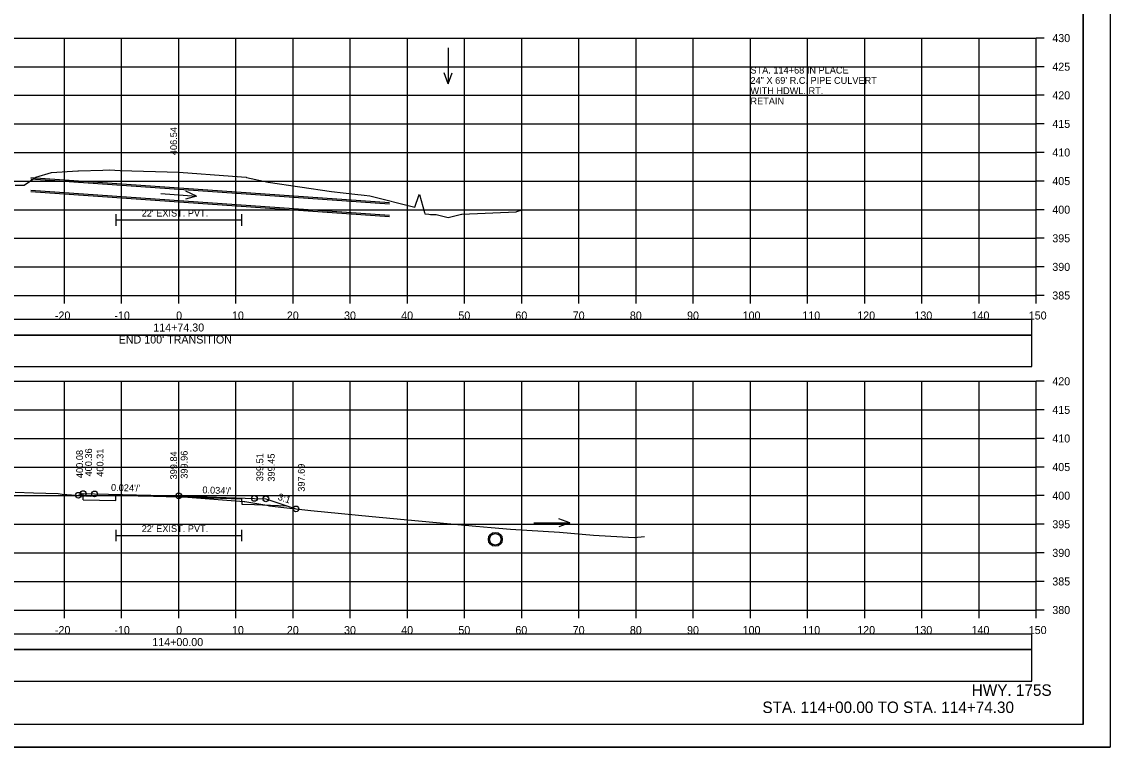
# Model space of a CAD drawing. Extents: x -37291014 to -37290680, y -936053 to -933067.
# Drawn here: x -37290870.6 to -37290680.2, y -933279.9 to -933153.1 of the extents above; entities that cross this region are included whole.
import ezdxf

# ---------------------------------------------------------------- set-up
doc = ezdxf.new("R2010")
doc.units = 0
for name, color, linetype in [('Default', 7, 'Continuous'), ('R_Alt Surface', 7, 'Continuous'), ('R_Axis', 7, 'Continuous'), ('R_Axis Annot', 7, 'Continuous'), ('R_Border', 7, 'Continuous'), ('R_Draft', 7, 'Continuous'), ('R_Exist Surface', 7, 'Continuous'), ('R_Fin Surface', 7, 'Continuous'), ('R_Grid', 7, 'Continuous'), ('R_No Plot', 7, 'Continuous'), ('R_Water', 7, 'Continuous'), ('R_Water Annot', 7, 'Continuous'), ('R_Xsect Elev', 7, 'Continuous'), ('R_Xsect Slope', 7, 'Continuous')]:
    doc.layers.add(name, color=color, linetype=linetype)

msp = doc.modelspace()

# ---------------------------------------------------------------- linework, layer by layer
at = {"layer": 'Default'}
for points in [[(-37290992.31, -933207.84), (-37290693.89, -933207.84), (-37290693.89, -933205.13), (-37290992.31, -933205.13)], [(-37290992.31, -933213.36), (-37290693.89, -933213.36), (-37290693.89, -933207.84), (-37290992.31, -933207.84)], [(-37290992.31, -933262.84), (-37290693.89, -933262.84), (-37290693.89, -933260.13), (-37290992.31, -933260.13)], [(-37290992.31, -933268.36), (-37290693.89, -933268.36), (-37290693.89, -933262.84), (-37290992.31, -933262.84)]]:
    msp.add_lwpolyline(points, close=True, dxfattribs=at)
at = {"layer": 'R_Alt Surface'}
msp.add_line((-37290859.82, -933236.66), (-37290859.82, -933235.57), dxfattribs=at)
for points in [[(-37290854.1, -933186.73), (-37290854.1, -933188.73)], [(-37290854.1, -933187.73), (-37290832.1, -933187.73)], [(-37290832.1, -933186.73), (-37290832.1, -933188.73)], [(-37290859.82, -933236.66), (-37290854.1, -933236.79), (-37290854.1, -933235.87), (-37290843.1, -933236.13), (-37290832.1, -933236.51), (-37290832.09, -933237.43), (-37290829.87, -933237.5), (-37290824.24, -933237.69)], [(-37290854.1, -933241.89), (-37290854.1, -933243.89)], [(-37290854.1, -933242.89), (-37290832.1, -933242.89)], [(-37290832.1, -933241.89), (-37290832.1, -933243.89)]]:
    msp.add_lwpolyline(points, dxfattribs=at)
at = {"layer": 'R_Axis'}
for p, q in [((-37290693.1, -933200.93), (-37290693.1, -933155.93)), ((-37290691.7, -933155.93), (-37290693.1, -933155.93)), ((-37290691.7, -933160.93), (-37290693.1, -933160.93)), ((-37290691.7, -933165.93), (-37290693.1, -933165.93)), ((-37290691.7, -933170.93), (-37290693.1, -933170.93)), ((-37290691.7, -933175.93), (-37290693.1, -933175.93)), ((-37290691.7, -933180.93), (-37290693.1, -933180.93)), ((-37290691.7, -933185.93), (-37290693.1, -933185.93)), ((-37290691.7, -933190.93), (-37290693.1, -933190.93)), ((-37290691.7, -933195.93), (-37290693.1, -933195.93)), ((-37290993.1, -933200.93), (-37290693.1, -933200.93)), ((-37290863.1, -933202.33), (-37290863.1, -933200.93)), ((-37290853.1, -933202.33), (-37290853.1, -933200.93)), ((-37290843.1, -933202.33), (-37290843.1, -933200.93)), ((-37290833.1, -933202.33), (-37290833.1, -933200.93)), ((-37290823.1, -933202.33), (-37290823.1, -933200.93)), ((-37290813.1, -933202.33), (-37290813.1, -933200.93)), ((-37290803.1, -933202.33), (-37290803.1, -933200.93)), ((-37290793.1, -933202.33), (-37290793.1, -933200.93)), ((-37290783.1, -933202.33), (-37290783.1, -933200.93)), ((-37290773.1, -933202.33), (-37290773.1, -933200.93)), ((-37290763.1, -933202.33), (-37290763.1, -933200.93)), ((-37290753.1, -933202.33), (-37290753.1, -933200.93)), ((-37290743.1, -933202.33), (-37290743.1, -933200.93)), ((-37290733.1, -933202.33), (-37290733.1, -933200.93)), ((-37290723.1, -933202.33), (-37290723.1, -933200.93)), ((-37290713.1, -933202.33), (-37290713.1, -933200.93)), ((-37290703.1, -933202.33), (-37290703.1, -933200.93)), ((-37290693.1, -933202.33), (-37290693.1, -933200.93)), ((-37290691.7, -933200.93), (-37290693.1, -933200.93)), ((-37290693.1, -933255.93), (-37290693.1, -933215.93)), ((-37290691.7, -933215.93), (-37290693.1, -933215.93)), ((-37290691.7, -933220.93), (-37290693.1, -933220.93)), ((-37290691.7, -933225.93), (-37290693.1, -933225.93)), ((-37290691.7, -933230.93), (-37290693.1, -933230.93)), ((-37290691.7, -933235.93), (-37290693.1, -933235.93)), ((-37290691.7, -933240.93), (-37290693.1, -933240.93)), ((-37290691.7, -933245.93), (-37290693.1, -933245.93)), ((-37290691.7, -933250.93), (-37290693.1, -933250.93)), ((-37290993.1, -933255.93), (-37290693.1, -933255.93)), ((-37290863.1, -933257.33), (-37290863.1, -933255.93)), ((-37290853.1, -933257.33), (-37290853.1, -933255.93)), ((-37290843.1, -933257.33), (-37290843.1, -933255.93)), ((-37290833.1, -933257.33), (-37290833.1, -933255.93)), ((-37290823.1, -933257.33), (-37290823.1, -933255.93)), ((-37290813.1, -933257.33), (-37290813.1, -933255.93)), ((-37290803.1, -933257.33), (-37290803.1, -933255.93)), ((-37290793.1, -933257.33), (-37290793.1, -933255.93)), ((-37290783.1, -933257.33), (-37290783.1, -933255.93)), ((-37290773.1, -933257.33), (-37290773.1, -933255.93)), ((-37290763.1, -933257.33), (-37290763.1, -933255.93)), ((-37290753.1, -933257.33), (-37290753.1, -933255.93)), ((-37290743.1, -933257.33), (-37290743.1, -933255.93)), ((-37290733.1, -933257.33), (-37290733.1, -933255.93)), ((-37290723.1, -933257.33), (-37290723.1, -933255.93)), ((-37290713.1, -933257.33), (-37290713.1, -933255.93)), ((-37290703.1, -933257.33), (-37290703.1, -933255.93)), ((-37290693.1, -933257.33), (-37290693.1, -933255.93)), ((-37290691.7, -933255.93), (-37290693.1, -933255.93))]:
    msp.add_line(p, q, dxfattribs=at)
at = {"layer": 'R_Border'}
for q in [(-37290684.92, -933070.47), (-37291001.1, -933275.93)]:
    msp.add_line((-37290684.92, -933275.93), q, dxfattribs=at)
at = {"layer": 'R_Exist Surface'}
for points in [[(-37290871.7, -933181.67), (-37290870.16, -933181.64), (-37290868.08, -933180.25), (-37290865.37, -933179.43), (-37290860.73, -933179.12), (-37290860.7, -933179.11), (-37290860.65, -933179.11), (-37290856.39, -933179.04), (-37290855.21, -933178.99), (-37290853.33, -933179.06), (-37290843.06, -933179.39), (-37290833.72, -933180.09), (-37290831.31, -933180.26), (-37290831.28, -933180.28), (-37290827.47, -933181.13), (-37290816.37, -933182.75), (-37290812.33, -933183.23), (-37290810.69, -933183.42), (-37290809.68, -933183.49), (-37290801.82, -933185.46), (-37290801.11, -933183.45), (-37290801, -933183.3), (-37290800.11, -933186.44), (-37290800.04, -933186.64), (-37290799.34, -933186.7), (-37290799.08, -933186.77), (-37290798.06, -933186.78), (-37290795.95, -933187.29), (-37290793.66, -933186.71), (-37290793.64, -933186.71), (-37290793.61, -933186.7), (-37290784.11, -933186.29), (-37290783.97, -933186.22), (-37290783.02, -933185.97)], [(-37290871.74, -933235.3), (-37290868.53, -933235.45), (-37290864.2, -933235.58), (-37290863.51, -933235.65), (-37290858.58, -933236), (-37290856.57, -933235.91), (-37290855.02, -933235.83), (-37290850.19, -933235.96), (-37290843.03, -933236.09), (-37290837.7, -933236.47), (-37290831.68, -933236.93), (-37290831.54, -933236.95), (-37290827.72, -933237.61), (-37290827.25, -933237.69), (-37290825.27, -933237.93), (-37290820.02, -933238.54), (-37290809.25, -933239.56), (-37290805.51, -933239.93), (-37290791.14, -933241.29), (-37290788.45, -933241.5), (-37290785.09, -933241.77), (-37290776.49, -933242.32), (-37290770.55, -933242.81), (-37290763.45, -933243.24), (-37290761.64, -933243.05)]]:
    msp.add_lwpolyline(points, dxfattribs=at)
at = {"layer": 'R_Fin Surface'}
msp.add_lwpolyline([(-37290860.65, -933235.85), (-37290859.82, -933235.57), (-37290857.82, -933235.62), (-37290843.1, -933235.97), (-37290829.87, -933236.42), (-37290827.87, -933236.48), (-37290822.61, -933238.24)], dxfattribs=at)
at = {"layer": 'R_Grid'}
for p, q in [((-37290993.1, -933155.93), (-37290693.1, -933155.93)), ((-37290863.1, -933200.93), (-37290863.1, -933155.93)), ((-37290853.1, -933200.93), (-37290853.1, -933155.93)), ((-37290843.1, -933200.93), (-37290843.1, -933155.93)), ((-37290833.1, -933200.93), (-37290833.1, -933155.93)), ((-37290823.1, -933200.93), (-37290823.1, -933155.93)), ((-37290813.1, -933200.93), (-37290813.1, -933155.93)), ((-37290803.1, -933200.93), (-37290803.1, -933155.93)), ((-37290793.1, -933200.93), (-37290793.1, -933155.93)), ((-37290783.1, -933200.93), (-37290783.1, -933155.93)), ((-37290773.1, -933200.93), (-37290773.1, -933155.93)), ((-37290763.1, -933200.93), (-37290763.1, -933155.93)), ((-37290753.1, -933200.93), (-37290753.1, -933155.93)), ((-37290743.1, -933200.93), (-37290743.1, -933155.93)), ((-37290733.1, -933200.93), (-37290733.1, -933155.93)), ((-37290723.1, -933200.93), (-37290723.1, -933155.93)), ((-37290713.1, -933200.93), (-37290713.1, -933155.93)), ((-37290703.1, -933200.93), (-37290703.1, -933155.93)), ((-37290693.1, -933200.93), (-37290693.1, -933155.93)), ((-37290993.1, -933160.93), (-37290693.1, -933160.93)), ((-37290993.1, -933165.93), (-37290693.1, -933165.93)), ((-37290993.1, -933170.93), (-37290693.1, -933170.93)), ((-37290993.1, -933175.93), (-37290693.1, -933175.93)), ((-37290993.1, -933180.93), (-37290693.1, -933180.93)), ((-37290993.1, -933185.93), (-37290693.1, -933185.93)), ((-37290993.1, -933190.93), (-37290693.1, -933190.93)), ((-37290993.1, -933195.93), (-37290693.1, -933195.93)), ((-37290993.1, -933200.93), (-37290693.1, -933200.93)), ((-37290993.1, -933215.93), (-37290693.1, -933215.93)), ((-37290863.1, -933255.93), (-37290863.1, -933215.93)), ((-37290853.1, -933255.93), (-37290853.1, -933215.93)), ((-37290843.1, -933255.93), (-37290843.1, -933215.93)), ((-37290833.1, -933255.93), (-37290833.1, -933215.93)), ((-37290823.1, -933255.93), (-37290823.1, -933215.93)), ((-37290813.1, -933255.93), (-37290813.1, -933215.93)), ((-37290803.1, -933255.93), (-37290803.1, -933215.93)), ((-37290793.1, -933255.93), (-37290793.1, -933215.93)), ((-37290783.1, -933255.93), (-37290783.1, -933215.93)), ((-37290773.1, -933255.93), (-37290773.1, -933215.93)), ((-37290763.1, -933255.93), (-37290763.1, -933215.93)), ((-37290753.1, -933255.93), (-37290753.1, -933215.93)), ((-37290743.1, -933255.93), (-37290743.1, -933215.93)), ((-37290733.1, -933255.93), (-37290733.1, -933215.93)), ((-37290723.1, -933255.93), (-37290723.1, -933215.93)), ((-37290713.1, -933255.93), (-37290713.1, -933215.93)), ((-37290703.1, -933255.93), (-37290703.1, -933215.93)), ((-37290693.1, -933255.93), (-37290693.1, -933215.93)), ((-37290993.1, -933220.93), (-37290693.1, -933220.93)), ((-37290993.1, -933225.93), (-37290693.1, -933225.93)), ((-37290993.1, -933230.93), (-37290693.1, -933230.93)), ((-37290993.1, -933235.93), (-37290693.1, -933235.93)), ((-37290993.1, -933240.93), (-37290693.1, -933240.93)), ((-37290993.1, -933245.93), (-37290693.1, -933245.93)), ((-37290993.1, -933250.93), (-37290693.1, -933250.93)), ((-37290993.1, -933255.93), (-37290693.1, -933255.93))]:
    msp.add_line(p, q, dxfattribs=at)
at = {"layer": 'R_No Plot'}
for p, q in [((-37290868.99, -933180.33), (-37290806.25, -933184.7)), ((-37290868.99, -933182.75), (-37290806.25, -933187.11)), ((-37291013.5, -933279.91), (-37290680.17, -933279.91))]:
    msp.add_line(p, q, dxfattribs=at)
for points in [[(-37291013.51, -933066.58), (-37290680.17, -933066.58), (-37290680.17, -933279.91), (-37291013.51, -933279.91)], [(-37290767.18, -933070.47), (-37290747.56, -933070.47), (-37290747.56, -933080.35), (-37290731.45, -933080.35), (-37290708.25, -933080.35), (-37290708.25, -933104.68), (-37290684.92, -933104.68), (-37290684.92, -933275.93), (-37291001.1, -933275.93), (-37291001.1, -933070.47)]]:
    msp.add_lwpolyline(points, close=True, dxfattribs=at)
for centre, radius in [((-37290860.65, -933235.85), 0.5), ((-37290859.82, -933235.57), 0.5), ((-37290857.82, -933235.62), 0.5), ((-37290843.1, -933235.97), 0.5), ((-37290829.87, -933236.42), 0.5), ((-37290827.87, -933236.48), 0.5), ((-37290822.61, -933238.24), 0.5), ((-37290787.73, -933243.57), 1.21)]:
    msp.add_circle(centre, radius, dxfattribs=at)
at = {"layer": 'R_Water'}
for p, q in [((-37290868.99, -933180.54), (-37290806.25, -933184.91)), ((-37290868.99, -933182.54), (-37290806.25, -933186.91))]:
    msp.add_line(p, q, dxfattribs=at)
msp.add_circle((-37290787.73, -933243.57), 1, dxfattribs=at)
at = {"layer": 'R_Water Annot'}
for p, q in [((-37290795.95, -933157.62), (-37290795.95, -933163.9)), ((-37290795.95, -933163.9), (-37290796.65, -933161.98)), ((-37290795.95, -933163.9), (-37290795.25, -933161.98)), ((-37290846.24, -933183.11), (-37290839.97, -933183.54)), ((-37290839.97, -933183.54), (-37290841.93, -933184.11)), ((-37290839.97, -933183.54), (-37290841.84, -933182.71)), ((-37290780.97, -933240.66), (-37290774.68, -933240.66)), ((-37290774.68, -933240.66), (-37290776.6, -933239.96)), ((-37290774.68, -933240.66), (-37290776.6, -933241.36))]:
    msp.add_line(p, q, dxfattribs=at)
at = {"layer": 'R_Xsect Elev'}
for p, q in [((-37290843.1, -933179.39), (-37290843.1, -933169.39)), ((-37290843.1, -933236.09), (-37290843.1, -933226.09))]:
    msp.add_line(p, q, dxfattribs=at)

# ---------------------------------------------------------------- texts
at = {"layer": 'R_Axis Annot'}
for s, p in [('430', (-37290690.3, -933156.63)), ('425', (-37290690.3, -933161.63)), ('420', (-37290690.3, -933166.63)), ('415', (-37290690.3, -933171.63)), ('410', (-37290690.3, -933176.63)), ('405', (-37290690.3, -933181.63)), ('400', (-37290690.3, -933186.63)), ('395', (-37290690.3, -933191.63)), ('390', (-37290690.3, -933196.63)), ('385', (-37290690.3, -933201.63)), ('-20', (-37290864.76, -933205.13)), ('-10', (-37290854.36, -933205.13)), ('0', (-37290843.56, -933205.13)), ('10', (-37290833.79, -933205.13)), ('20', (-37290824.19, -933205.13)), ('30', (-37290814.19, -933205.13)), ('40', (-37290804.19, -933205.13)), ('50', (-37290794.19, -933205.13)), ('60', (-37290784.22, -933205.13)), ('70', (-37290774.19, -933205.13)), ('80', (-37290764.19, -933205.13)), ('90', (-37290754.19, -933205.13)), ('100', (-37290744.47, -933205.13)), ('110', (-37290734.02, -933205.13)), ('120', (-37290724.42, -933205.13)), ('130', (-37290714.42, -933205.13)), ('140', (-37290704.42, -933205.13)), ('150', (-37290694.42, -933205.13)), ('114+74.30', (-37290847.56, -933207.23)), ("END 100' TRANSITION", (-37290853.61, -933209.33)), ('420', (-37290690.3, -933216.63)), ('415', (-37290690.3, -933221.63)), ('410', (-37290690.3, -933226.63)), ('405', (-37290690.3, -933231.63)), ('400', (-37290690.3, -933236.63)), ('395', (-37290690.3, -933241.63)), ('390', (-37290690.3, -933246.63)), ('385', (-37290690.3, -933251.63)), ('380', (-37290690.3, -933256.63)), ('-20', (-37290864.76, -933260.13)), ('-10', (-37290854.36, -933260.13)), ('0', (-37290843.56, -933260.13)), ('10', (-37290833.79, -933260.13)), ('20', (-37290824.19, -933260.13)), ('30', (-37290814.19, -933260.13)), ('40', (-37290804.19, -933260.13)), ('50', (-37290794.19, -933260.13)), ('60', (-37290784.22, -933260.13)), ('70', (-37290774.19, -933260.13)), ('80', (-37290764.19, -933260.13)), ('90', (-37290754.19, -933260.13)), ('100', (-37290744.47, -933260.13)), ('110', (-37290734.02, -933260.13)), ('120', (-37290724.42, -933260.13)), ('130', (-37290714.42, -933260.13)), ('140', (-37290704.42, -933260.13)), ('150', (-37290694.42, -933260.13)), ('114+00.00', (-37290847.73, -933262.23))]:
    msp.add_text(s, height=1.4, dxfattribs=at).set_placement(p)
at = {"layer": 'R_Draft'}
for s, p in [('HWY. 175S', (-37290704.39, -933270.93)), ('STA. 114+00.00 TO STA. 114+74.30', (-37290741.01, -933273.93))]:
    msp.add_text(s, height=2, dxfattribs=at).set_placement(p)
at = {"layer": 'R_Water'}
for p in [(-37290849.58, -933187.13), (-37290849.58, -933242.29)]:
    msp.add_text("22' EXIST. PVT.", height=1.2, dxfattribs=at).set_placement(p)
at = {"layer": 'R_Water Annot'}
for s, p in [('STA. 114+68 IN PLACE', (-37290743.1, -933162.13)), ('24" X 69\' R.C. PIPE CULVERT', (-37290743.1, -933163.93)), ('WITH HDWL. RT.', (-37290743.1, -933165.73)), ('RETAIN', (-37290743.1, -933167.53))]:
    msp.add_text(s, height=1.2, dxfattribs=at).set_placement(p)
at = {"layer": 'R_Xsect Elev'}
for s, p in [('406.54', (-37290843.4, -933176.39)), ('400.08', (-37290859.84, -933232.85)), ('400.36', (-37290858.27, -933232.57)), ('400.31', (-37290856.27, -933232.62)), ('399.84', (-37290843.4, -933233.09)), ('399.96', (-37290841.55, -933232.97)), ('399.51', (-37290828.32, -933233.42)), ('399.45', (-37290826.32, -933233.48)), ('397.69', (-37290821.06, -933235.24))]:
    msp.add_text(s, height=1.2, rotation=90, dxfattribs=at).set_placement(p)
at = {"layer": 'R_Xsect Slope'}
for s, rotation, p in [("0.024'/'", 358.6482, (-37290854.96, -933235.09)), ("0.034'/'", 358.0546, (-37290838.98, -933235.51)), ('3:1', 341.5651, (-37290825.87, -933236.62))]:
    msp.add_text(s, height=1.2, rotation=rotation, dxfattribs=at).set_placement(p)

doc.saveas('drawing.dxf')
